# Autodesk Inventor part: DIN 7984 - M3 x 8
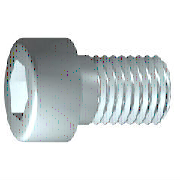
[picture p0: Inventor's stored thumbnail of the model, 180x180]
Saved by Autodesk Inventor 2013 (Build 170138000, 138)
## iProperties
IsCustomPart: 0
Created: 2012-02
Part Number: DIN 7984 - M3 x 8
Material: Stahl, weich
Description: Zylinderkopfschraube
Document SubType Name: Modeling
Standard: DIN 7984
Designer: rYan
Standard Revision: 1985
Standards Organization: DIN
Language: de-DE
Size Designation: M3 x 8
Categories: <MemberInstance><Categories><Category DisplayName="Verbindungselemente" InternalName="e4da775c-781d-43d5-af7c-5136215cf5a6" Mnemonic="FSTN"><Category DisplayNam
Density: 7.86 g/cm^3
Mass: 0.76435 g
Surface Area: 1.64326 cm^2
Volume: 0.0972456 cm^3
Author: rYan
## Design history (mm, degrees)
sketch "Skizze1"
  geometry: L1 (0.167, 0)-(8, 0); L2 (8, 0)-(8, 1.5); L3 (8, 1.5)-(1.5, 1.5); L4 (1.5, 1.5)-(1.193, 1.5); L5 (1.193, 1.5)-(0, 1.5); L6 (0, 1.5)-(0, 2.75); L7 (0, 2.75)-(-2, 2.75); L8 (-2, 2.75)-(-2, 1.155); L9 (-2, 1.155)-(-0.5, 1.155); L10 (-0.5, 1.155)-(0.167, 0); L11 (-4, 0)-(10, 0) reference; L12 (0, -0.55)-(0, 3.3) reference; L13 (1.5, 1.5)-(0, 1.5)
  constraints: 22 end point, 6 parallel, 2 collinear, 2 perpendicular, 1 horizontal, 1 point on line
  dimensions: "d1" = 6.5 distance from line of L3.end L2 (= GEL); "d2" = 0.30683 distance of L4.end L3.end (computed from GAL); "d3" = 2 distance between parallel lines of L8 L6 (= KOH); "d4" = 1.5 distance of L8.end L9.end (= INTI); "d5" = 60 deg angle of L10 L1; "d6" = 3 diameter of L3 L1 (= GD); "d7" = 3 diameter of L5 L1 (= BDM); "d8" = 2.3094 diameter of L9 L1 (= 1.1547 x SW); "d9" = 5.5 diameter of L7 L1 (= KOD); "d26" = 8 distance between parallel lines of L12 L2 (= NLG)
revolve "Körper" sketch "Skizze1" stored, may be unused: angle "d10" = 90 deg
sketch "Skizze2"
  geometry: L1 (0, -3.85)-(0, 3.85) reference; L2 (-3.85, 0)-(3.85, 0) reference; L3 (1.155, 0)-(0.577, -1); L4 (0.577, -1)-(-0.577, -1); L5 (-0.577, -1)-(-1.155, 0); L6 (-1.155, 0)-(-0.577, 1); L7 (-0.577, 1)-(0.577, 1); L8 (0.577, 1)-(1.155, 0); 2 further points
  constraints: 12 end point, 1 coincident, 1 horizontal alignment, 1 point on line, 12 other
extrude "Loch" join sketch "Skizze2" stored distance "d11" = 10; taper "d12" = 0 deg
workplane "Work Plane1"
fillet "Fillet2" dims "d30" = 0.1 (= R)
body "Solid1"
fillet "Rundung1" dims "d17" = 0.3 (= RR)
feature "Gewinde" dims "d13" = 6.5 (= GEL), "d14" = 0
chamfer "Fase1" distance "d15" = 0.30673 (= -0.5 x SPD + 0.5 x GD); stored, may be unused: second distance "d16" = 0.30673 (= GUL), angle "d27" = 45 deg
other parameters: "GD" = 3 (= NND) [user parameter; used in 2 equation terms], "NLG" = 8 [user parameter; used in 1 equation term], "GEL" = 6.5 [user parameter; used in 2 equation terms], "KOD" = 5.5 [user parameter; used in 1 equation term], "KOH" = 2 [user parameter; used in 1 equation term], "INTI" = 1.5 [user parameter; used in 1 equation term], "GAL" = 0.30673 (= 0.61345 x PTC) [user parameter; used in 1 equation term], "GUL" = 0.30673 (= 0.61345 x PTC) [user parameter; used in 1 equation term], "BDM" = 3 (= NND) [user parameter; used in 1 equation term], "SW" = 2 [user parameter; used in 2 equation terms], "RR" = 0.3 [user parameter; used in 1 equation term], "SPD" = 2.38655 (= NND - 1.2269 x PTC) [user parameter; used in 1 equation term], "d19" = 0, "d28" = 0, "d29" = 0, "R" = 0.1 [user parameter; used in 1 equation term], "TOA" = 30 deg [user parameter], "GD1" = 2.38655 (= THREADDIA - 1.2269 x PTC) [user parameter], "THREADDIA" = 3 [user parameter; used in 1 equation term], "FAWI" = 45 deg [user parameter], "ANG" = 120 deg [user parameter], "PTC" = 0.5 [user parameter; used in 5 equation terms], "NND" = 3 [user parameter; used in 3 equation terms], "E0" = 2.31 (= 1.155 x SW) [user parameter]
